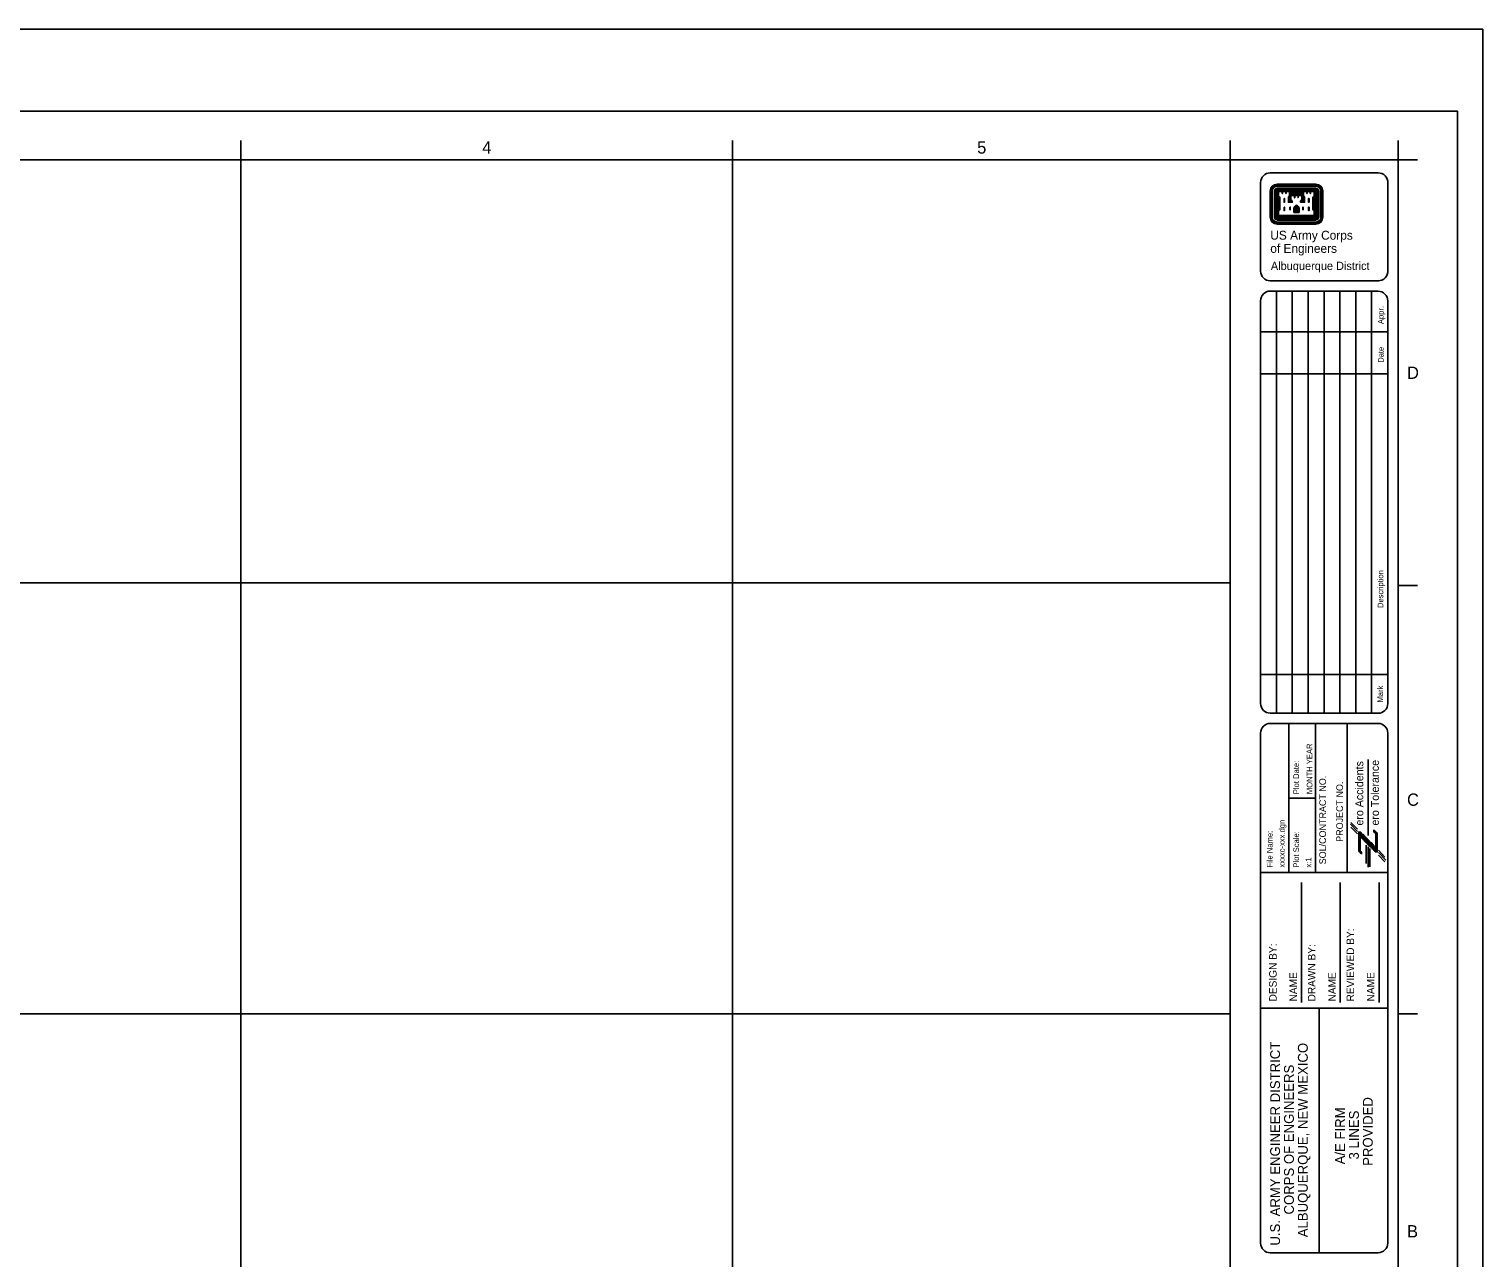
# Model space of a CAD drawing. Extents: x -0.19 to 2.81, y 0.03 to 2.03.
# Drawn here: x 1.329 to 2.806, y 0.783 to 2.032 of the extents above; entities that cross this region are included whole.
import ezdxf

# ---------------------------------------------------------------- set-up
doc = ezdxf.new("R2010")
doc.units = 0
for name, color, linetype in [('G-ANNO-NPLT', 7, 'Continuous'), ('G-ANNO-SYMB', 7, 'Continuous'), ('G-ANNO-TEXT', 7, 'Continuous'), ('G-ANNO-TTBL', 7, 'Continuous'), ('S-ANNO-TEXT', 7, 'Continuous')]:
    doc.layers.add(name, color=color, linetype=linetype)

msp = doc.modelspace()

# ---------------------------------------------------------------- linework, layer by layer
at = {"layer": 'G-ANNO-NPLT'}
for p, q in [((2.5495, 0.1551), (2.5495, 1.9077)), ((1.5442, 1.8993), (1.5442, 0.1724)), ((2.0436, 1.8993), (2.0436, 0.1724)), ((2.5495, 1.4696), (0.0565, 1.4696)), ((2.5495, 1.0314), (0.0565, 1.0314))]:
    msp.add_line(p, q, dxfattribs=at)
at = {"layer": 'G-ANNO-SYMB'}
for p, q in [((2.5903, 1.8679), (2.5903, 1.841)), ((2.5906, 1.8679), (2.5906, 1.841)), ((2.5913, 1.8679), (2.5913, 1.841)), ((2.5919, 1.8679), (2.5919, 1.841)), ((2.5923, 1.8679), (2.5923, 1.841)), ((2.5946, 1.8679), (2.5946, 1.841)), ((2.5952, 1.8679), (2.5952, 1.841)), ((2.5959, 1.8679), (2.5959, 1.841)), ((2.5962, 1.8679), (2.5962, 1.841)), ((2.5969, 1.8679), (2.5969, 1.841)), ((2.6366, 1.8748), (2.5972, 1.8748)), ((2.6366, 1.8744), (2.5972, 1.8744)), ((2.6366, 1.8738), (2.5972, 1.8738)), ((2.6366, 1.8731), (2.5972, 1.8731)), ((2.6366, 1.8728), (2.5972, 1.8728)), ((2.6366, 1.8705), (2.5972, 1.8705)), ((2.6366, 1.8698), (2.5972, 1.8698)), ((2.6366, 1.8692), (2.5972, 1.8692)), ((2.6366, 1.8689), (2.5972, 1.8689)), ((2.6366, 1.8682), (2.5972, 1.8682)), ((2.5975, 1.8679), (2.5975, 1.8413)), ((2.5978, 1.8679), (2.5978, 1.842)), ((2.5985, 1.862), (2.5985, 1.8485)), ((2.611, 1.8675), (2.6231, 1.8675)), ((2.611, 1.8672), (2.6231, 1.8672)), ((2.611, 1.8666), (2.6231, 1.8666)), ((2.611, 1.8659), (2.6231, 1.8659)), ((2.611, 1.8653), (2.6231, 1.8653)), ((2.611, 1.8649), (2.6231, 1.8649)), ((2.611, 1.8643), (2.6231, 1.8643)), ((2.6352, 1.862), (2.6352, 1.8485)), ((2.6359, 1.8679), (2.6359, 1.842)), ((2.6366, 1.8679), (2.6366, 1.8413)), ((2.6369, 1.8679), (2.6369, 1.841)), ((2.6375, 1.8679), (2.6375, 1.841)), ((2.6382, 1.8679), (2.6382, 1.841)), ((2.6385, 1.8679), (2.6385, 1.841)), ((2.6392, 1.8679), (2.6392, 1.841)), ((2.6415, 1.8679), (2.6415, 1.841)), ((2.6421, 1.8679), (2.6421, 1.841)), ((2.6428, 1.8679), (2.6428, 1.841)), ((2.6431, 1.8679), (2.6431, 1.841)), ((2.6438, 1.8679), (2.6438, 1.841)), ((2.5991, 1.8616), (2.5991, 1.8492)), ((2.6142, 1.8459), (2.6142, 1.8502)), ((2.6149, 1.8459), (2.6149, 1.8502)), ((2.6156, 1.8459), (2.6156, 1.8502)), ((2.6159, 1.8459), (2.6159, 1.8502)), ((2.6165, 1.8459), (2.6165, 1.8502)), ((2.6172, 1.8459), (2.6172, 1.8502)), ((2.6179, 1.8459), (2.6179, 1.8502)), ((2.6185, 1.8459), (2.6185, 1.8502)), ((2.6188, 1.8459), (2.6188, 1.8502)), ((2.6195, 1.8459), (2.6195, 1.8502)), ((2.6349, 1.8616), (2.6349, 1.8492)), ((2.6366, 1.8406), (2.5972, 1.8406)), ((2.6366, 1.8403), (2.5972, 1.8403)), ((2.6366, 1.8397), (2.5972, 1.8397)), ((2.6366, 1.839), (2.5972, 1.839)), ((2.6366, 1.8383), (2.5972, 1.8383)), ((2.6366, 1.836), (2.5972, 1.836)), ((2.6366, 1.8357), (2.5972, 1.8357)), ((2.6366, 1.8351), (2.5972, 1.8351)), ((2.6366, 1.8344), (2.5972, 1.8344)), ((2.6366, 1.8341), (2.5972, 1.8341)), ((2.6366, 1.8413), (2.5975, 1.8413)), ((2.6359, 1.842), (2.5978, 1.842)), ((2.6142, 1.8459), (2.6195, 1.8459)), ((2.6898, 1.2126), (2.6898, 1.2899)), ((2.6717, 1.2241), (2.6791, 1.2165)), ((2.6722, 1.2259), (2.6791, 1.2191)), ((2.6722, 1.2211), (2.6791, 1.2143)), ((2.6803, 1.1966), (2.6803, 1.2165)), ((2.6806, 1.1963), (2.6806, 1.2165)), ((2.6808, 1.1961), (2.6808, 1.2168)), ((2.6808, 1.1961), (2.6808, 1.2168)), ((2.6811, 1.1958), (2.6811, 1.2168)), ((2.6813, 1.1956), (2.6813, 1.2168)), ((2.6813, 1.1953), (2.6813, 1.2165)), ((2.6816, 1.1953), (2.6816, 1.2165)), ((2.6818, 1.1953), (2.6818, 1.2163)), ((2.6818, 1.2115), (2.6818, 1.2163)), ((2.6821, 1.2112), (2.6821, 1.216)), ((2.6823, 1.2112), (2.6823, 1.2158)), ((2.6823, 1.211), (2.6823, 1.2155)), ((2.6826, 1.2107), (2.6826, 1.2155)), ((2.6826, 1.2105), (2.6826, 1.2153)), ((2.6826, 1.2105), (2.6826, 1.2153)), ((2.6828, 1.2102), (2.6828, 1.215)), ((2.6831, 1.2102), (2.6831, 1.2148)), ((2.6831, 1.2102), (2.6831, 1.2145)), ((2.6834, 1.2097), (2.6834, 1.2145)), ((2.6839, 1.2095), (2.6839, 1.2143)), ((2.6839, 1.2092), (2.6839, 1.2143)), ((2.6841, 1.2092), (2.6841, 1.214)), ((2.6844, 1.209), (2.6844, 1.214)), ((2.6846, 1.2087), (2.6846, 1.2138)), ((2.6846, 1.2084), (2.6846, 1.2135)), ((2.6849, 1.2084), (2.6849, 1.2135)), ((2.6851, 1.2082), (2.6851, 1.2132)), ((2.6851, 1.2079), (2.6851, 1.213)), ((2.6854, 1.2077), (2.6854, 1.213)), ((2.6856, 1.2077), (2.6856, 1.2127)), ((2.6856, 1.2074), (2.6856, 1.2125)), ((2.6859, 1.2072), (2.6859, 1.2122)), ((2.6861, 1.2072), (2.6861, 1.2122)), ((2.6861, 1.2067), (2.6861, 1.212)), ((2.6864, 1.2064), (2.6864, 1.2117)), ((2.6864, 1.2064), (2.6864, 1.2117)), ((2.6957, 1.216), (2.6957, 1.2183)), ((2.696, 1.2158), (2.696, 1.2181)), ((2.6962, 1.2158), (2.6962, 1.2178)), ((2.6965, 1.2155), (2.6965, 1.2178)), ((2.6965, 1.2153), (2.6965, 1.2175)), ((2.6967, 1.2153), (2.6967, 1.2173)), ((2.697, 1.215), (2.697, 1.217)), ((2.697, 1.2148), (2.697, 1.217)), ((2.6972, 1.2145), (2.6972, 1.2168)), ((2.6975, 1.1958), (2.6975, 1.2165)), ((2.6975, 1.1956), (2.6975, 1.2165)), ((2.6977, 1.1953), (2.6977, 1.2163)), ((2.698, 1.1953), (2.698, 1.216)), ((2.698, 1.1953), (2.698, 1.2158)), ((2.6982, 1.1953), (2.6982, 1.2158)), ((2.6985, 1.1953), (2.6985, 1.2155)), ((2.6985, 1.1953), (2.6985, 1.2153)), ((2.6988, 1.1956), (2.6988, 1.2153)), ((2.6818, 1.1953), (2.6818, 1.1971)), ((2.6821, 1.1948), (2.6821, 1.1968)), ((2.6823, 1.1945), (2.6823, 1.1968)), ((2.6869, 1.2062), (2.6869, 1.2115)), ((2.6869, 1.2062), (2.6869, 1.2112)), ((2.6871, 1.2059), (2.6871, 1.2112)), ((2.6871, 1.2059), (2.6871, 1.211)), ((2.6874, 1.2057), (2.6874, 1.2107)), ((2.6876, 1.2057), (2.6876, 1.2105)), ((2.6876, 1.2054), (2.6876, 1.2105)), ((2.6879, 1.2052), (2.6879, 1.2102)), ((2.6879, 1.2029), (2.6879, 1.1842)), ((2.6881, 1.2049), (2.6881, 1.2102)), ((2.6881, 1.2049), (2.6881, 1.2102)), ((2.6884, 1.2047), (2.6884, 1.2097)), ((2.6887, 1.2044), (2.6887, 1.2095)), ((2.6889, 1.2042), (2.6889, 1.2092)), ((2.6889, 1.2042), (2.6889, 1.2092)), ((2.6892, 1.2039), (2.6892, 1.209)), ((2.6894, 1.2039), (2.6894, 1.2087)), ((2.6894, 1.2036), (2.6894, 1.2084)), ((2.6897, 1.2034), (2.6897, 1.2084)), ((2.6897, 1.2011), (2.6897, 1.1804)), ((2.6899, 1.2031), (2.6899, 1.2082)), ((2.6899, 1.2031), (2.6899, 1.2082)), ((2.6902, 1.2029), (2.6902, 1.2079)), ((2.6902, 1.2026), (2.6902, 1.2077)), ((2.6904, 1.2024), (2.6904, 1.2074)), ((2.6907, 1.2024), (2.6907, 1.2074)), ((2.6907, 1.2021), (2.6907, 1.2072)), ((2.6909, 1.2019), (2.6909, 1.2067)), ((2.6912, 1.2019), (2.6912, 1.2064)), ((2.6914, 1.2016), (2.6914, 1.2064)), ((2.6914, 1.2014), (2.6914, 1.2062)), ((2.6914, 1.1994), (2.6914, 1.1806)), ((2.6917, 1.2011), (2.6917, 1.2062)), ((2.6919, 1.2011), (2.6919, 1.2059)), ((2.6919, 1.2009), (2.6919, 1.2059)), ((2.6924, 1.2006), (2.6924, 1.2057)), ((2.6927, 1.2004), (2.6927, 1.2057)), ((2.6932, 1.2004), (2.6932, 1.2054)), ((2.6932, 1.2001), (2.6932, 1.2052)), ((2.6935, 1.1999), (2.6935, 1.2049)), ((2.6937, 1.1996), (2.6937, 1.2049)), ((2.6937, 1.1996), (2.6937, 1.2047)), ((2.694, 1.1994), (2.694, 1.2044)), ((2.694, 1.1994), (2.694, 1.2042)), ((2.694, 1.1991), (2.694, 1.2042)), ((2.694, 1.1988), (2.694, 1.2039)), ((2.6945, 1.1986), (2.6945, 1.2039)), ((2.6945, 1.1986), (2.6945, 1.2036)), ((2.6947, 1.1983), (2.6947, 1.2034)), ((2.6947, 1.1983), (2.6947, 1.2031)), ((2.695, 1.1983), (2.695, 1.2031)), ((2.6952, 1.1981), (2.6952, 1.2029)), ((2.6955, 1.1978), (2.6955, 1.2026)), ((2.6955, 1.1978), (2.6955, 1.2024)), ((2.6957, 1.1976), (2.6957, 1.2024)), ((2.6957, 1.1973), (2.6957, 1.2021)), ((2.696, 1.1971), (2.696, 1.2019)), ((2.6962, 1.1971), (2.6962, 1.2019)), ((2.6965, 1.1968), (2.6965, 1.2016)), ((2.6965, 1.1966), (2.6965, 1.2014)), ((2.6967, 1.1963), (2.6967, 1.2011)), ((2.697, 1.1963), (2.697, 1.2011)), ((2.697, 1.1961), (2.697, 1.2009)), ((2.6972, 1.1961), (2.6972, 1.2006)), ((2.7068, 1.1905), (2.7003, 1.1976)), ((2.6823, 1.1943), (2.6823, 1.1966)), ((2.6826, 1.1943), (2.6826, 1.1963)), ((2.6826, 1.194), (2.6826, 1.1961)), ((2.6826, 1.1938), (2.6826, 1.1961)), ((2.6828, 1.1938), (2.6828, 1.1958)), ((2.6831, 1.1935), (2.6831, 1.1956)), ((2.7003, 1.1953), (2.7076, 1.1875)), ((2.7003, 1.1925), (2.7068, 1.186))]:
    msp.add_line(p, q, dxfattribs=at)
for points in [[(2.5985, 1.8679), (2.5985, 1.8626), (2.5995, 1.8616), (2.5995, 1.8492), (2.5985, 1.8479), (2.5985, 1.8423), (2.6356, 1.8423), (2.6356, 1.8479), (2.6343, 1.8492), (2.6343, 1.8616), (2.6356, 1.8626), (2.6356, 1.8679), (2.6306, 1.8679), (2.6267, 1.8679), (2.6234, 1.8679), (2.6234, 1.8626), (2.6244, 1.8616), (2.6244, 1.857), (2.6218, 1.857), (2.6218, 1.8574), (2.6231, 1.8587), (2.6231, 1.8636), (2.6182, 1.8636), (2.6142, 1.8636), (2.611, 1.8636), (2.611, 1.8587), (2.6119, 1.8574), (2.6119, 1.857), (2.6093, 1.857), (2.6093, 1.8616), (2.6106, 1.8626), (2.6106, 1.8679), (2.6057, 1.8679), (2.6018, 1.8679), (2.5985, 1.8679)], [(2.5988, 1.8672), (2.5988, 1.863), (2.6001, 1.8616), (2.6001, 1.8488), (2.5988, 1.8479), (2.5988, 1.8429), (2.6349, 1.8429), (2.6349, 1.8479), (2.6336, 1.8488), (2.6336, 1.8616), (2.6349, 1.863), (2.6349, 1.8672), (2.6313, 1.8672), (2.6313, 1.8653), (2.631, 1.8653), (2.631, 1.8672), (2.6277, 1.8672), (2.6277, 1.8653), (2.6274, 1.8653), (2.6274, 1.8672), (2.6241, 1.8672), (2.6241, 1.863), (2.6251, 1.8616), (2.6251, 1.8564), (2.6211, 1.8564), (2.6211, 1.8577), (2.6224, 1.8587), (2.6224, 1.8633), (2.6188, 1.8633), (2.6188, 1.861), (2.6185, 1.861), (2.6185, 1.8633), (2.6152, 1.8633), (2.6152, 1.861), (2.6149, 1.861), (2.6149, 1.8633), (2.6113, 1.8633), (2.6113, 1.8587), (2.6126, 1.8577), (2.6126, 1.8564), (2.6087, 1.8564), (2.6087, 1.8616), (2.61, 1.863), (2.61, 1.8672), (2.6064, 1.8672), (2.6064, 1.8653), (2.606, 1.8653), (2.606, 1.8672), (2.6028, 1.8672), (2.6028, 1.8653), (2.6024, 1.8653), (2.6024, 1.8672), (2.5988, 1.8672)], [(2.6044, 1.8603), (2.6044, 1.8564), (2.6047, 1.8564), (2.6047, 1.8603), (2.6044, 1.8603)], [(2.6044, 1.8515), (2.6044, 1.8479), (2.6047, 1.8479), (2.6047, 1.8515), (2.6044, 1.8515)], [(2.6103, 1.8616), (2.61, 1.8613), (2.61, 1.8577), (2.611, 1.8577), (2.6103, 1.8584), (2.6103, 1.8616)], [(2.6103, 1.8515), (2.6103, 1.8488), (2.6106, 1.8488), (2.6106, 1.8515), (2.6103, 1.8515)], [(2.6238, 1.8616), (2.6241, 1.8613), (2.6241, 1.8577), (2.6228, 1.8577), (2.6234, 1.8584), (2.6234, 1.8616)], [(2.6238, 1.8515), (2.6238, 1.8488), (2.6234, 1.8488), (2.6234, 1.8515), (2.6238, 1.8515)], [(2.6297, 1.8603), (2.6297, 1.8564), (2.6293, 1.8564), (2.6293, 1.8603), (2.6297, 1.8603)], [(2.6297, 1.8515), (2.6297, 1.8479), (2.6293, 1.8479), (2.6293, 1.8515), (2.6297, 1.8515)]]:
    msp.add_lwpolyline(points, dxfattribs=at)
for centre, radius, start, end in [((2.5972, 1.8678), 0.00696, 90, 180), ((2.5972, 1.8678), 0.00656, 90, 180), ((2.5972, 1.8678), 0.006, 90, 180), ((2.5972, 1.8678), 0.00543, 90, 180), ((2.5972, 1.8678), 0.00487, 90, 180), ((2.5972, 1.8678), 0.00261, 90, 180), ((2.5972, 1.8678), 0.00205, 90, 180), ((2.5972, 1.8678), 0.00148, 90, 180), ((2.5972, 1.8678), 0.000919, 90, 180), ((2.5972, 1.8678), 0.000355, 90, 180), ((2.6367, 1.8678), 0.00696, 0, 90), ((2.6367, 1.8678), 0.00656, 0, 90), ((2.6367, 1.8678), 0.006, 0, 90), ((2.6367, 1.8678), 0.00543, 0, 90), ((2.6367, 1.8678), 0.00487, 0, 90), ((2.6367, 1.8678), 0.00261, 0, 90), ((2.6367, 1.8678), 0.00205, 0, 90), ((2.6367, 1.8678), 0.00148, 0, 90), ((2.6367, 1.8678), 0.000919, 0, 90), ((2.6367, 1.8678), 0.000355, 0, 90), ((2.6179, 1.8498), 0.00361, 105.6681, 176.0575), ((2.6179, 1.8498), 0.00305, 103.4698, 176.0575), ((2.6179, 1.8498), 0.00248, 103.4698, 176.0575), ((2.6179, 1.8498), 0.00192, 103.4698, 176.0575), ((2.616, 1.8498), 0.00135, 3.9425, 76.5302), ((2.616, 1.8498), 0.00192, 3.9425, 76.5302), ((2.616, 1.8498), 0.00248, 3.9425, 76.5302), ((2.6179, 1.8498), 0.00135, 103.4698, 176.0575), ((2.616, 1.8498), 0.00305, 3.9425, 76.5302), ((2.616, 1.8498), 0.00361, 3.9425, 74.3949), ((2.5972, 1.8411), 0.00696, 180, 270), ((2.5972, 1.8411), 0.00656, 180, 270), ((2.5972, 1.8411), 0.006, 180, 270), ((2.5972, 1.8411), 0.00543, 180, 270), ((2.5972, 1.8411), 0.00487, 180, 270), ((2.5972, 1.8411), 0.00261, 180, 270), ((2.5972, 1.8411), 0.00205, 180, 270), ((2.5972, 1.8411), 0.00148, 180, 270), ((2.5972, 1.8411), 0.000919, 180, 270), ((2.5972, 1.8411), 0.000355, 180, 270), ((2.6367, 1.8411), 0.00696, 270, 0), ((2.6367, 1.8411), 0.00261, 270, 0), ((2.6367, 1.8411), 0.00205, 270, 0), ((2.6367, 1.8411), 0.00148, 270, 0), ((2.6367, 1.8411), 0.000919, 270, 0), ((2.6367, 1.8411), 0.000355, 270, 0), ((2.6367, 1.8411), 0.00487, 270, 360), ((2.6367, 1.8411), 0.00543, 270, 360), ((2.6367, 1.8411), 0.006, 270, 360), ((2.6367, 1.8411), 0.00656, 270, 360)]:
    msp.add_arc(centre, radius, start, end, dxfattribs=at)
at = {"layer": 'G-ANNO-TEXT'}
msp.add_line((2.6362, 1.2506), (2.609, 1.2506), dxfattribs=at)
at = {"layer": 'G-ANNO-TTBL'}
for p, q in [((1.5442, 1.919), (1.5442, 1.8993)), ((2.0436, 1.919), (2.0436, 1.8993)), ((2.5495, 1.919), (2.5495, 1.8993)), ((2.7202, 1.919), (2.7202, 0.1527)), ((0.0368, 1.8993), (2.7398, 1.8993)), ((2.5804, 1.7247), (2.7097, 1.7247)), ((2.5804, 1.682), (2.7097, 1.682)), ((2.7202, 1.4667), (2.7398, 1.4667)), ((2.5804, 1.3763), (2.7097, 1.3763)), ((2.609, 1.3265), (2.609, 1.1751)), ((2.6362, 1.3265), (2.6362, 1.1751)), ((2.6686, 1.3265), (2.6686, 1.1751)), ((2.7097, 1.1751), (2.5804, 1.1751)), ((2.6221, 1.0428), (2.6221, 1.1647)), ((2.6614, 1.0428), (2.6614, 1.1647)), ((2.7008, 1.0428), (2.7008, 1.1647)), ((2.7097, 1.0371), (2.5804, 1.0371)), ((2.6399, 1.0371), (2.6399, 0.7884)), ((2.7202, 1.0314), (2.7398, 1.0314))]:
    msp.add_line(p, q, dxfattribs=at)
for points in [[(2.8064, 2.0324), (-0.1936, 2.0324), (-0.1936, 0.0324), (2.8064, 0.0324)], [(-0.053, 1.9491), (2.7804, 1.9491), (2.7804, 0.1157), (-0.053, 0.1157)]]:
    msp.add_lwpolyline(points, close=True, dxfattribs=at)
for points in [[(2.5903, 1.8863), (2.6999, 1.8863)], [(2.7097, 1.877), (2.7097, 1.7857)], [(2.5804, 1.7863), (2.5804, 1.8764)], [(2.7006, 1.7765), (2.5903, 1.7765)], [(2.6999, 1.7661), (2.5903, 1.7661)], [(2.5966, 1.7661), (2.5966, 1.3369)], [(2.6127, 1.7661), (2.6127, 1.3369)], [(2.6288, 1.7661), (2.6288, 1.3369)], [(2.6449, 1.7661), (2.6449, 1.3369)], [(2.661, 1.7661), (2.661, 1.3369)], [(2.6771, 1.7661), (2.6771, 1.3369)], [(2.6932, 1.7661), (2.6932, 1.3369)], [(2.5804, 1.7562), (2.5804, 1.3467)], [(2.7097, 1.3461), (2.7097, 1.7562)], [(2.5903, 1.3369), (2.6999, 1.3369)], [(2.5804, 1.3167), (2.5804, 0.7982)], [(2.6999, 1.3265), (2.5894, 1.3265)], [(2.7097, 0.7982), (2.7097, 1.3167)], [(2.5903, 0.7884), (2.6999, 0.7884)]]:
    msp.add_lwpolyline(points, dxfattribs=at)
for centre, start, end in [((2.5903, 1.8764), 90, 180), ((2.6999, 1.8764), 356.3757, 90), ((2.5903, 1.7863), 180, 270), ((2.6999, 1.7863), 270, 3.6243), ((2.5903, 1.7562), 90, 180), ((2.6999, 1.7561), 0, 90), ((2.5903, 1.3468), 180, 270), ((2.6999, 1.3467), 270, 0), ((2.5903, 1.3167), 90, 180), ((2.6999, 1.3167), 0, 90), ((2.5903, 0.7982), 180, 270), ((2.6999, 0.7983), 270, 0)]:
    msp.add_arc(centre, 0.00984, start, end, dxfattribs=at)

# ---------------------------------------------------------------- texts
at = {"layer": 'G-ANNO-SYMB'}
for s, p in [('ero Accidents', (2.6848, 1.2227)), ('ero Tolerance', (2.7007, 1.2227))]:
    msp.add_text(s, height=0.008086, rotation=90, dxfattribs=at).set_placement(p)
at = {"layer": 'G-ANNO-TEXT'}
for s, height, p in [('4', 0.0125, (1.7894, 1.9058)), ('5', 0.0125, (2.2924, 1.9058)), ('US Army Corps', 0.009029, (2.5903, 1.8183)), ('of Engineers', 0.009029, (2.5903, 1.8049)), ('Albuquerque District', 0.00833, (2.5909, 1.7875)), ('D', 0.0125, (2.7293, 1.6768)), ('C', 0.0125, (2.7293, 1.2428)), ('B', 0.0125, (2.7293, 0.804))]:
    msp.add_text(s, height=height, dxfattribs=at).set_placement(p)
for s, height, p in [('Appr.', 0.00574, (2.7055, 1.7325)), ('Date', 0.00574, (2.7055, 1.6932)), ('Description', 0.005741, (2.7051, 1.4439)), ('Mark', 0.00558, (2.7048, 1.3478)), ('MONTH YEAR', 0.00578, (2.6331, 1.2546)), ('Plot Date:', 0.00579, (2.6195, 1.2546)), ('SOL/CONTRACT NO.', 0.006809, (2.6469, 1.1833)), ('PROJECT NO.', 0.006809, (2.6642, 1.2062)), ('File Name:', 0.00579, (2.5926, 1.18)), ('Plot Scale:', 0.005785, (2.6195, 1.18)), ('REVIEWED BY:', 0.007687, (2.6755, 1.0439)), ('DESIGN BY:', 0.00769, (2.5968, 1.0439)), ('DRAWN BY:', 0.00768, (2.6362, 1.0439)), ('U.S. ARMY ENGINEER DISTRICT', 0.01, (2.6002, 0.7957)), ('ALBUQUERQUE, NEW MEXICO', 0.01, (2.6284, 0.8042)), ('CORPS OF ENGINEERS', 0.01, (2.6143, 0.8273)), ('PROVIDED', 0.01, (2.6944, 0.8768)), ('A/E FIRM', 0.01, (2.6662, 0.8783)), ('3 LINES', 0.01, (2.6803, 0.8832))]:
    msp.add_text(s, height=height, rotation=90, dxfattribs=at).set_placement(p)
at = {"layer": 'S-ANNO-TEXT'}
for s, height, p in [('xxxxc-xxx.dgn', 0.005785, (2.605, 1.18)), ('x:1', 0.00579, (2.6319, 1.18)), ('NAME', 0.00769, (2.6175, 1.0439)), ('NAME', 0.00768, (2.6569, 1.0439)), ('NAME', 0.00769, (2.6962, 1.0439))]:
    msp.add_text(s, height=height, rotation=90, dxfattribs=at).set_placement(p)

doc.saveas('drawing.dxf')
